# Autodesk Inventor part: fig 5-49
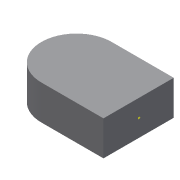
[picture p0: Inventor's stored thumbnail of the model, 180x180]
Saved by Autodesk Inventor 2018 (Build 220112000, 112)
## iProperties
Created: 2010-02
Part Number: fig 5-49
Document SubType Name: Modeling
Designer: CADSoft
Density: 1 g/cm^3
Material: Generic
Appearance: Default
Author: CADSoft
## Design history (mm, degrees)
sketch "Sketch1"
  geometry: L1 (-17.92, 20.292)-(0, 20.292); L2 (0, 20.292)-(0, 0); L3 (0, 0)-(-17.92, 0); A1 r 10.146 centre (-17.92, 10.146) between (-17.92, 20.292) and (-17.92, 0)
  constraints: 6 end point, 2 horizontal, 2 point on circle, 2 tangent, 1 centre point, 1 vertical
extrude "Extrusion1" new body sketch "Sketch1" distance "d0" = 10; taper "d1" = 0 deg
workpoint "Work Point1"
body "Solid1"
